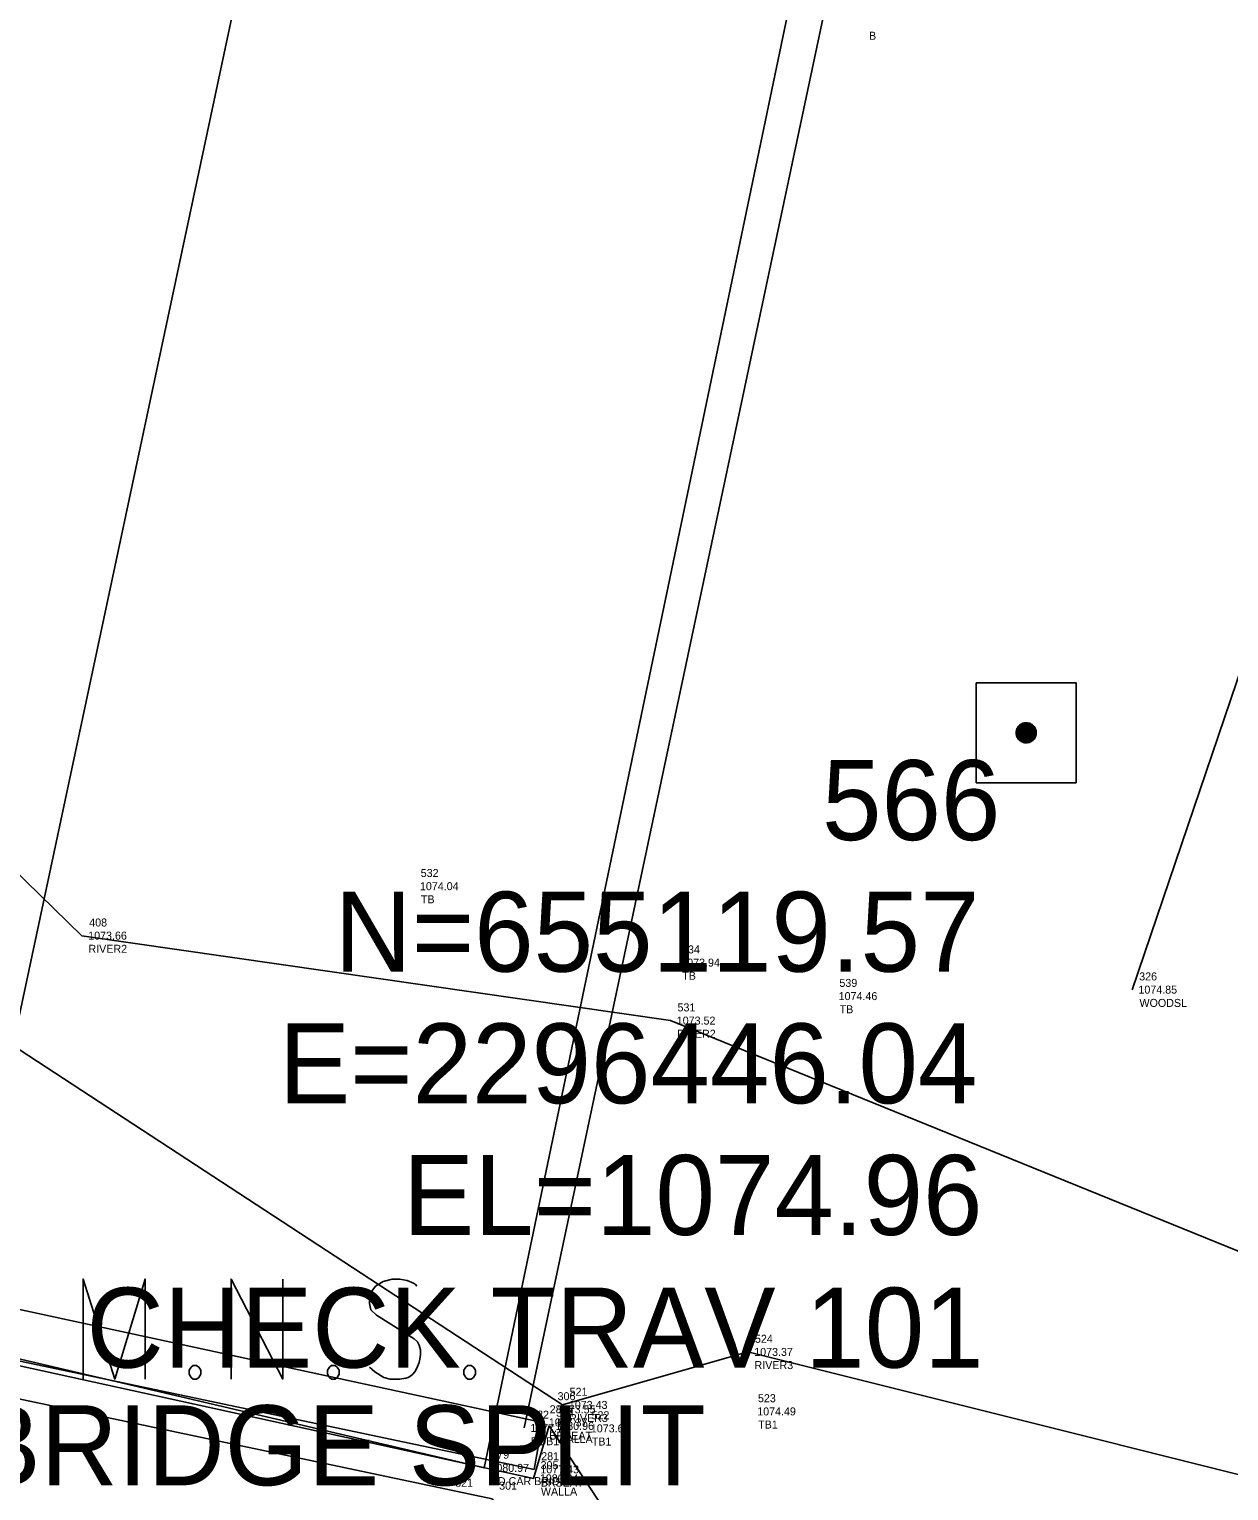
# Model space of a CAD drawing. Extents: x 2296145 to 2296886, y 654772 to 655516.
# Drawn here: x 2296426.05 to 2296450.05, y 655104.34 to 655133.59 of the extents above; entities that cross this region are included whole.
import ezdxf

# ---------------------------------------------------------------- set-up
doc = ezdxf.new("R2010")
doc.units = 0
for name, color, linetype in [('BR_X_SV_Abut', 7, 'Continuous'), ('BR_X_SV_Beam_Seat', 7, 'Continuous'), ('BR_X_SV_Bottom_of_Beam', 7, 'Continuous'), ('BR_X_SV_Deck_Top', 7, 'Continuous'), ('GE_P_CL', 7, 'Continuous'), ('HY_X_Water_Edge', 7, 'Continuous'), ('SV_P_Control_Cells_Set', 7, 'Continuous'), ('SV_X_Text_Comment', 7, 'Continuous'), ('SV_X_Text_Description', 7, 'Continuous'), ('VG_X_Tree_Line_Rt', 7, 'Continuous')]:
    doc.layers.add(name, color=color, linetype=linetype)

msp = doc.modelspace()

# ---------------------------------------------------------------- linework, layer by layer
at = {"layer": 'BR_X_SV_Abut'}
msp.add_lwpolyline([(2296398.69, 655112.66), (2296398.8, 655113.62), (2296386.39, 655105.51), (2296387.43, 655104.05), (2296398.84, 655111.61), (2296399.22, 655111.8), (2296410.13, 655109.5), (2296435.31, 655104.18), (2296443.05, 655092.31), (2296444.57, 655093.33), (2296436.45, 655105.64), (2296436.14, 655104.59), (2296424.57, 655107.12), (2296412.58, 655109.7), (2296412.83, 655110.81), (2296408.27, 655111.68), (2296408.05, 655110.65), (2296398.69, 655112.66)], dxfattribs=at)
at = {"layer": 'BR_X_SV_Beam_Seat'}
msp.add_lwpolyline([(2296436.15, 655104.77), (2296436.32, 655105.71), (2296413.07, 655110.73), (2296412.78, 655109.69), (2296436.15, 655104.77)], dxfattribs=at)
at = {"layer": 'BR_X_SV_Bottom_of_Beam'}
msp.add_line((2296442.03, 655134.27), (2296435.95, 655105.6), dxfattribs=at)
at = {"layer": 'BR_X_SV_Deck_Top'}
msp.add_lwpolyline([(2296414.16, 655109.72), (2296420.3, 655140.04), (2296441.54, 655135.42), (2296435.15, 655104.8), (2296414.16, 655109.72)], dxfattribs=at)
at = {"layer": 'GE_P_CL'}
msp.add_line((2296418.26, 655078.221), (2296466.082, 655302.878), dxfattribs=at)
at = {"layer": 'HY_X_Water_Edge'}
for points in [[(2296416.41, 655125.87), (2296427.1, 655115.45), (2296438.88, 655113.75), (2296455.14, 655107.15), (2296470.14, 655110.14), (2296483.16, 655114.46), (2296505.87, 655117.72), (2296524.75, 655113.51), (2296529.66, 655112.86), (2296527.46, 655097.14), (2296527.77, 655091.65), (2296537.59, 655080.06), (2296547.88, 655070.84), (2296565.32, 655067.84), (2296572.93, 655070.08), (2296591.06, 655072.44), (2296602.66, 655064.53), (2296612.47, 655062.37)], [(2296415.18, 655120.14), (2296436.72, 655106.06), (2296440.43, 655107.12), (2296455.23, 655103.42), (2296466.38, 655103.34), (2296476.23, 655105.31), (2296484.61, 655110.23), (2296506.74, 655112.45), (2296523.97, 655109.66), (2296523.47, 655103.28), (2296521.32, 655098.85), (2296521.47, 655087.43), (2296530.274, 655073.763), (2296544.68, 655066.35), (2296555.12, 655060.29), (2296566.1, 655060.19), (2296573.18, 655065.46), (2296579.09, 655067.52), (2296583.65, 655067.14), (2296594.14, 655066.37), (2296601.39, 655060.67), (2296610.28, 655055.67)]]:
    msp.add_lwpolyline(points, dxfattribs=at)
at = {"layer": 'SV_P_Control_Cells_Set'}
for points in [[(2296445.001, 655120.511), (2296446.999, 655120.511), (2296446.999, 655118.511), (2296445.001, 655118.511), (2296445.001, 655120.511)], [(2296427.123, 655106.579), (2296427.123, 655108.579), (2296427.757, 655106.579), (2296428.363, 655108.579), (2296428.363, 655106.579)], [(2296430.086, 655106.579), (2296430.086, 655108.579), (2296431.119, 655106.579), (2296431.119, 655108.579)], [(2296433.806, 655108.437), (2296433.778, 655108.469), (2296433.737, 655108.5), (2296433.613, 655108.548), (2296433.461, 655108.579), (2296433.351, 655108.579), (2296433.31, 655108.579), (2296433.131, 655108.532), (2296432.979, 655108.437), (2296432.882, 655108.311), (2296432.855, 655108.185), (2296432.855, 655108.091), (2296432.882, 655107.965), (2296432.993, 655107.855), (2296433.751, 655107.382), (2296433.819, 655107.32), (2296433.847, 655107.257), (2296433.875, 655107.162), (2296433.875, 655107.068), (2296433.861, 655106.973), (2296433.847, 655106.91), (2296433.819, 655106.831), (2296433.792, 655106.768), (2296433.764, 655106.721), (2296433.723, 655106.674), (2296433.682, 655106.642), (2296433.627, 655106.611), (2296433.585, 655106.595), (2296433.461, 655106.579), (2296433.268, 655106.579), (2296433.144, 655106.611), (2296432.965, 655106.721), (2296432.855, 655106.816)], [(2296429.328, 655106.847), (2296429.397, 655106.847), (2296429.438, 655106.816), (2296429.479, 655106.753), (2296429.479, 655106.674), (2296429.438, 655106.611), (2296429.397, 655106.579), (2296429.328, 655106.579), (2296429.286, 655106.611), (2296429.245, 655106.674), (2296429.245, 655106.753), (2296429.286, 655106.816), (2296429.328, 655106.847)], [(2296432.097, 655106.847), (2296432.166, 655106.847), (2296432.207, 655106.816), (2296432.249, 655106.753), (2296432.249, 655106.674), (2296432.207, 655106.611), (2296432.166, 655106.579), (2296432.097, 655106.579), (2296432.056, 655106.611), (2296432.015, 655106.674), (2296432.015, 655106.753), (2296432.056, 655106.816), (2296432.097, 655106.847)], [(2296434.825, 655106.847), (2296434.894, 655106.847), (2296434.936, 655106.816), (2296434.977, 655106.753), (2296434.977, 655106.674), (2296434.936, 655106.611), (2296434.894, 655106.579), (2296434.825, 655106.579), (2296434.784, 655106.611), (2296434.743, 655106.674), (2296434.743, 655106.753), (2296434.784, 655106.816), (2296434.825, 655106.847)]]:
    msp.add_lwpolyline(points, dxfattribs=at)
for points in [[(2296445.899, 655119.685), (2296446.117, 655119.674), (2296445.884, 655119.674)], [(2296445.918, 655119.694), (2296446.099, 655119.685), (2296445.899, 655119.685)], [(2296445.899, 655119.685), (2296446.099, 655119.685), (2296446.117, 655119.674)], [(2296445.934, 655119.701), (2296446.084, 655119.694), (2296445.918, 655119.694)], [(2296445.918, 655119.694), (2296446.084, 655119.694), (2296446.099, 655119.685)], [(2296445.956, 655119.706), (2296446.063, 655119.701), (2296445.934, 655119.701)], [(2296445.934, 655119.701), (2296446.063, 655119.701), (2296446.084, 655119.694)], [(2296445.971, 655119.71), (2296446.048, 655119.706), (2296445.956, 655119.706)], [(2296445.956, 655119.706), (2296446.048, 655119.706), (2296446.063, 655119.701)], [(2296446.01, 655119.712), (2296446.022, 655119.71), (2296445.971, 655119.71)], [(2296445.971, 655119.71), (2296446.022, 655119.71), (2296446.048, 655119.706)], [(2296445.803, 655119.548), (2296446.2, 655119.529), (2296445.799, 655119.529)], [(2296445.799, 655119.529), (2296446.202, 655119.51), (2296445.799, 655119.51)], [(2296445.799, 655119.529), (2296446.2, 655119.529), (2296446.202, 655119.51)], [(2296445.799, 655119.51), (2296446.2, 655119.491), (2296445.799, 655119.491)], [(2296445.799, 655119.51), (2296446.202, 655119.51), (2296446.2, 655119.491)], [(2296445.799, 655119.491), (2296446.198, 655119.472), (2296445.803, 655119.472)], [(2296445.799, 655119.491), (2296446.2, 655119.491), (2296446.198, 655119.472)], [(2296445.806, 655119.567), (2296446.198, 655119.548), (2296445.803, 655119.548)], [(2296445.803, 655119.548), (2296446.198, 655119.548), (2296446.2, 655119.529)], [(2296445.803, 655119.472), (2296446.193, 655119.453), (2296445.806, 655119.453)], [(2296445.803, 655119.472), (2296446.198, 655119.472), (2296446.193, 655119.453)], [(2296445.814, 655119.585), (2296446.193, 655119.567), (2296445.806, 655119.567)], [(2296445.806, 655119.567), (2296446.193, 655119.567), (2296446.198, 655119.548)], [(2296445.806, 655119.453), (2296446.187, 655119.435), (2296445.814, 655119.435)], [(2296445.806, 655119.453), (2296446.193, 655119.453), (2296446.187, 655119.435)], [(2296445.821, 655119.602), (2296446.187, 655119.585), (2296445.814, 655119.585)], [(2296445.814, 655119.585), (2296446.187, 655119.585), (2296446.193, 655119.567)], [(2296445.814, 655119.435), (2296446.178, 655119.418), (2296445.821, 655119.418)], [(2296445.814, 655119.435), (2296446.187, 655119.435), (2296446.178, 655119.418)], [(2296445.831, 655119.619), (2296446.178, 655119.602), (2296445.821, 655119.602)], [(2296445.821, 655119.602), (2296446.178, 655119.602), (2296446.187, 655119.585)], [(2296445.821, 655119.418), (2296446.17, 655119.401), (2296445.831, 655119.401)], [(2296445.821, 655119.418), (2296446.178, 655119.418), (2296446.17, 655119.401)], [(2296445.841, 655119.635), (2296446.17, 655119.619), (2296445.831, 655119.619)], [(2296445.831, 655119.619), (2296446.17, 655119.619), (2296446.178, 655119.602)], [(2296445.831, 655119.401), (2296446.158, 655119.385), (2296445.841, 655119.385)], [(2296445.831, 655119.401), (2296446.17, 655119.401), (2296446.158, 655119.385)], [(2296445.855, 655119.649), (2296446.158, 655119.635), (2296445.841, 655119.635)], [(2296445.841, 655119.635), (2296446.158, 655119.635), (2296446.17, 655119.619)], [(2296445.841, 655119.385), (2296446.146, 655119.371), (2296445.855, 655119.371)], [(2296445.841, 655119.385), (2296446.158, 655119.385), (2296446.146, 655119.371)], [(2296445.868, 655119.663), (2296446.146, 655119.649), (2296445.855, 655119.649)], [(2296445.855, 655119.649), (2296446.146, 655119.649), (2296446.158, 655119.635)], [(2296445.884, 655119.674), (2296446.131, 655119.663), (2296445.868, 655119.663)], [(2296445.868, 655119.663), (2296446.131, 655119.663), (2296446.146, 655119.649)], [(2296445.884, 655119.674), (2296446.117, 655119.674), (2296446.131, 655119.663)], [(2296445.855, 655119.371), (2296446.131, 655119.357), (2296445.868, 655119.357)], [(2296445.855, 655119.371), (2296446.146, 655119.371), (2296446.131, 655119.357)], [(2296445.868, 655119.357), (2296446.117, 655119.346), (2296445.884, 655119.346)], [(2296445.868, 655119.357), (2296446.131, 655119.357), (2296446.117, 655119.346)], [(2296445.884, 655119.346), (2296446.099, 655119.335), (2296445.899, 655119.335)], [(2296445.884, 655119.346), (2296446.117, 655119.346), (2296446.099, 655119.335)], [(2296445.899, 655119.335), (2296446.084, 655119.326), (2296445.918, 655119.326)], [(2296445.899, 655119.335), (2296446.099, 655119.335), (2296446.084, 655119.326)], [(2296445.918, 655119.326), (2296446.063, 655119.319), (2296445.934, 655119.319)], [(2296445.918, 655119.326), (2296446.084, 655119.326), (2296446.063, 655119.319)], [(2296445.934, 655119.319), (2296446.048, 655119.314), (2296445.956, 655119.314)], [(2296445.934, 655119.319), (2296446.063, 655119.319), (2296446.048, 655119.314)], [(2296445.956, 655119.314), (2296446.022, 655119.31), (2296445.971, 655119.31)], [(2296445.956, 655119.314), (2296446.048, 655119.314), (2296446.022, 655119.31)], [(2296445.971, 655119.31), (2296446.022, 655119.31), (2296446.01, 655119.308)]]:
    msp.add_lwpolyline(points, close=True, dxfattribs=at)
at = {"layer": 'SV_X_Text_Comment'}
msp.add_circle((2296446.04, 655119.57), 0.1, dxfattribs=at)
at = {"layer": 'VG_X_Tree_Line_Rt'}
msp.add_lwpolyline([(2296539.59, 655418.52), (2296535.49, 655394.94), (2296529.46, 655368.9), (2296523.13, 655343.42), (2296514.01, 655318), (2296504.24, 655295.97), (2296495.24, 655272.43), (2296485.52, 655248.8), (2296477.02, 655226.99), (2296468.97, 655205.81), (2296463.95, 655180.7), (2296458.09, 655154.83), (2296457.7, 655144.44), (2296454.54, 655133.29), (2296448.12, 655114.37)], dxfattribs=at)

# ---------------------------------------------------------------- texts
at = {"layer": 'SV_X_Text_Comment'}
for s, height, p in [('B', 0.16, (2296442.854, 655133.378)), ('566', 1.6, (2296441.913, 655117.363)), ('532', 0.16, (2296433.881, 655116.625)), ('1074.04', 0.16, (2296433.866, 655116.361)), ('N=655119.57', 1.6, (2296432.156, 655114.73)), ('TB', 0.16, (2296433.885, 655116.098)), ('408', 0.16, (2296427.247, 655115.634)), ('1073.66', 0.16, (2296427.226, 655115.371)), ('RIVER2', 0.16, (2296427.232, 655115.108)), ('534', 0.16, (2296439.111, 655115.095)), ('1073.94', 0.16, (2296439.096, 655114.831)), ('TB', 0.16, (2296439.115, 655114.568)), ('326', 0.16, (2296448.261, 655114.555)), ('539', 0.16, (2296442.261, 655114.425)), ('1074.85', 0.16, (2296448.246, 655114.291)), ('1074.46', 0.16, (2296442.246, 655114.161)), ('WOODSL', 0.16, (2296448.267, 655114.025)), ('1073.52', 0.16, (2296439.006, 655113.671)), ('531', 0.16, (2296439.021, 655113.935)), ('TB', 0.16, (2296442.265, 655113.898)), ('E=2296446.04', 1.6, (2296431.043, 655112.096)), ('RIVER2', 0.16, (2296439.012, 655113.408)), ('EL=1074.96', 1.6, (2296433.524, 655109.462)), ('CHECK TRAV 101', 1.6, (2296427.193, 655106.807)), ('524', 0.16, (2296440.571, 655107.304)), ('1073.37', 0.16, (2296440.556, 655107.041)), ('RIVER3', 0.16, (2296440.562, 655106.778)), ('306', 0.16, (2296436.621, 655106.155)), ('521', 0.16, (2296436.861, 655106.244)), ('523', 0.16, (2296440.631, 655106.115)), ('322', 0.16, (2296436.091, 655105.785)), ('282', 0.16, (2296436.463, 655105.894)), ('304', 0.16, (2296436.591, 655105.825)), ('1073.55', 0.16, (2296436.606, 655105.891)), ('1073.43', 0.16, (2296436.846, 655105.981)), ('522', 0.16, (2296437.301, 655105.774)), ('1074.49', 0.16, (2296440.616, 655105.851)), ('1077.70', 0.16, (2296436.076, 655105.521)), ('1077.37', 0.16, (2296436.446, 655105.631)), ('1080.96', 0.16, (2296436.576, 655105.561)), ('B', 0.16, (2296436.614, 655105.628)), ('RIVER3', 0.16, (2296436.852, 655105.718)), ('1073.68', 0.16, (2296437.286, 655105.511)), ('TB1', 0.16, (2296440.635, 655105.588)), ('BOB1', 0.16, (2296436.084, 655105.255)), ('BRSEAT', 0.16, (2296436.454, 655105.366)), ('WALLA', 0.16, (2296436.597, 655105.298)), ('TB1', 0.16, (2296437.305, 655105.248)), ('279', 0.16, (2296435.293, 655104.984)), ('281', 0.16, (2296436.293, 655104.954)), ('1080.97', 0.16, (2296435.276, 655104.721)), ('305', 0.16, (2296436.281, 655104.775)), ('1077.43', 0.16, (2296436.276, 655104.691)), ('821', 0.16, (2296434.571, 655104.424)), ('BD CAR BRIDGE', 0.16, (2296435.284, 655104.456)), ('301', 0.16, (2296435.451, 655104.365)), ('1080.94', 0.16, (2296436.266, 655104.511)), ('BRSEAT', 0.16, (2296436.284, 655104.426)), ('WALLA', 0.16, (2296436.287, 655104.248))]:
    msp.add_text(s, height=height, dxfattribs=at).set_placement(p)
at = {"layer": 'SV_X_Text_Description'}
msp.add_text('BRIDGE SPLIT', height=1.6, dxfattribs=at).set_placement((2296424.846, 655104.453))

doc.saveas('drawing.dxf')
